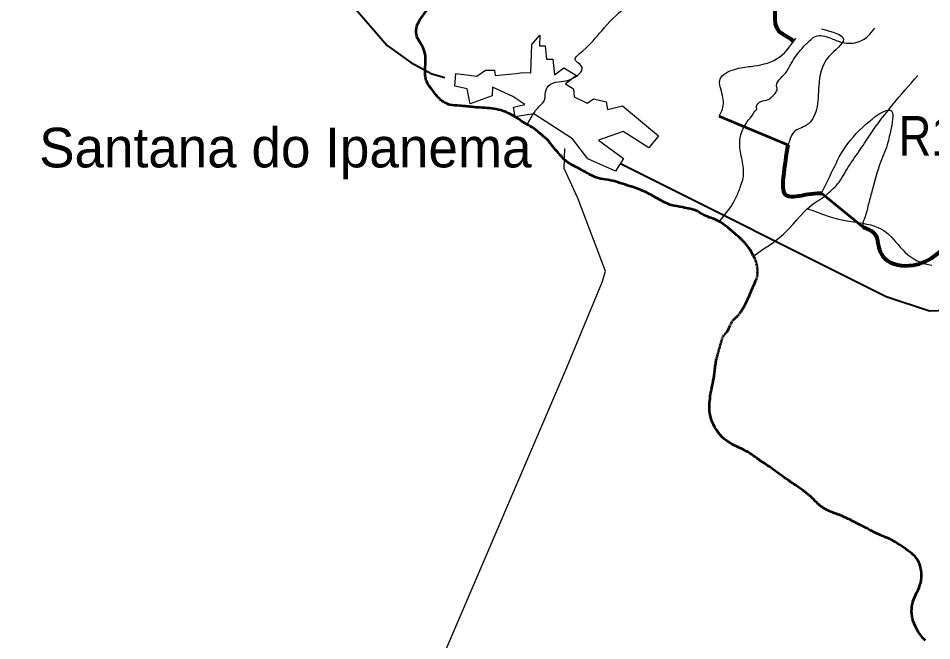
# Model space of a CAD drawing. Extents: x 553962 to 842807, y 8883888 to 9032388.
# Drawn here: x 685895 to 697411, y 8956803 to 8964653 of the extents above; entities that cross this region are included whole.
import ezdxf
from ezdxf.enums import TextEntityAlignment as Align

# ---------------------------------------------------------------- set-up
doc = ezdxf.new("R2010")
doc.units = 0
doc.header["$LTSCALE"] = 200
for name, color, linetype, lineweight in [('12', 7, 'Continuous', 25), ('21', 7, 'Continuous', 25), ('24', 7, 'Continuous', 25), ('50', 7, 'Continuous', 80), ('51', 7, 'Continuous', 25), ('9', 7, 'Continuous', 90)]:
    doc.layers.add(name, color=color, linetype=linetype, lineweight=lineweight)
doc.layers.add('41', color=7, linetype='Continuous')
doc.layers.add('53', color=7, linetype='Continuous')

msp = doc.modelspace()

# ---------------------------------------------------------------- linework, layer by layer
at = {"layer": '12', "lineweight": 40}
for points in [[(678613, 8973314.2), (678848.5, 8973159.5), (686496, 8968269.5), (688991.1, 8966516.2), (690142.8, 8964774.6), (690545.4, 8964311.7), (690844.1, 8964097.1), (691108, 8963953.4), (691274.5, 8963904.3)], [(693487.4, 8962819.8), (696836.9, 8961144.8), (697384.1, 8960961.8), (697603.7, 8960973.6), (697714.4, 8961082.3), (698321.2, 8961447.4), (698679, 8961567.8), (700187.3, 8961472.5), (701093.5, 8961547), (704410.2, 8961560.7)]]:
    msp.add_lwpolyline(points, dxfattribs=at)
at = {"layer": '12'}
msp.add_lwpolyline([(691240.8, 8956578.2), (692809.2, 8960246.9), (693257.6, 8961326.5), (693299.9, 8961463.3), (692951.1, 8962385.1), (692776, 8962756.9), (692786.9, 8963010.2)], dxfattribs=at)
at = {"layer": '21'}
msp.add_lwpolyline([(692254, 8963968.8), (692357.6, 8963964.3), (692367.8, 8964321.4), (692472.5, 8964438.4), (692467.8, 8964306.3), (692539.2, 8964305.6), (692555.6, 8964137.6), (692634.2, 8964137), (692654, 8963940.3), (692772.6, 8964028.6), (692932.6, 8963930.8), (692792.3, 8963824.8), (692895.4, 8963763.2), (692905.3, 8963663.2), (693068.9, 8963583.2), (693148, 8963636.1), (693304.9, 8963599), (693325.5, 8963502.4), (693511.7, 8963547.2), (693965.8, 8963171.8), (693843, 8963019.3), (693523.2, 8963225.7), (693211.4, 8963117.6), (693527.4, 8962882.7), (693426, 8962722.9), (693077.2, 8962879.5), (692882.8, 8963134.7), (692396, 8963446.1), (692159.9, 8963408.8), (692139.5, 8963534), (692282.7, 8963564.9), (692129.9, 8963666.3), (691873.7, 8963786.3), (691869.2, 8963675.7), (691593.2, 8963574.5), (691555.5, 8963764.1), (691398.6, 8963797.6), (691410.7, 8963954.6), (691678.4, 8963923.7), (691786.2, 8963997.8), (691900.5, 8963996.8), (691907.1, 8963932.5), (692171.7, 8963955.2)], close=True, dxfattribs=at)
at = {"layer": '24'}
for p, q in [((695185.1, 8961613.6), (695188.4, 8961605.4)), ((695191.4, 8961597.4), (695194.2, 8961589.4)), ((695196.8, 8961581.3), (695199.3, 8961572.8)), ((695201.7, 8961563.9), (695204, 8961554.7)), ((695206.1, 8961545.2), (695208.1, 8961535.5)), ((695210, 8961525.8), (695211.6, 8961516.2)), ((695213.1, 8961506.8), (695214.2, 8961497.7)), ((695208.8, 8961386.1), (695206.5, 8961378.2)), ((695212.3, 8961401), (695210.8, 8961393.7)), ((695214.3, 8961415.2), (695213.5, 8961408.2)), ((695215.5, 8961429.1), (695215, 8961422.2)), ((695215.1, 8961489), (695215.8, 8961480.6)), ((695216.2, 8961443), (695215.9, 8961436)), ((695216.2, 8961472.6), (695216.5, 8961464.9)), ((695216.5, 8961457.4), (695216.4, 8961450.1)), ((695203.7, 8961369.9), (695200.3, 8961361)), ((694988.2, 8960928.1), (694982.2, 8960920.1)), ((694881.6, 8960804.2), (694878.1, 8960796.7)), ((694888.3, 8960817.6), (694885, 8960811.2)), ((694895.4, 8960829.4), (694891.8, 8960823.7)), ((694903.2, 8960840.2), (694899.2, 8960834.8)), ((694912.2, 8960850.5), (694907.6, 8960845.4)), ((694922.1, 8960860.3), (694917.1, 8960855.5)), ((694932, 8960869.5), (694927, 8960865)), ((694941.4, 8960877.7), (694936.8, 8960873.7)), ((694950, 8960885.1), (694945.8, 8960881.5)), ((694958.2, 8960892.6), (694954.1, 8960888.7)), ((694966.8, 8960901.5), (694962.4, 8960896.8)), ((694976.7, 8960913), (694971.5, 8960906.9)), ((694825.8, 8960695.7), (694819.7, 8960688.5)), ((694874.5, 8960788.4), (694870.7, 8960779.5)), ((694761.3, 8960585.2), (694758.9, 8960576.3)), ((694767, 8960603.1), (694764, 8960594.1)), ((694773.6, 8960621), (694770.2, 8960612.1)), ((694781.6, 8960638.2), (694777.4, 8960629.7)), ((694790.9, 8960654), (694786, 8960646.3)), ((694801.8, 8960668.2), (694796.2, 8960661.2)), ((694813.6, 8960681.6), (694807.6, 8960674.9)), ((694728.6, 8960470), (694726.2, 8960462.1)), ((694733.8, 8960485.9), (694731.2, 8960478)), ((694738.8, 8960501.8), (694736.3, 8960493.8)), ((694743.7, 8960517.7), (694741.3, 8960509.7)), ((694748.1, 8960534), (694745.9, 8960525.8)), ((694752.2, 8960550.6), (694750.2, 8960542.3)), ((694756.5, 8960567.7), (694754.3, 8960559.1)), ((694699.2, 8960361.1), (694696.9, 8960351.9)), ((694703.5, 8960376.8), (694701.4, 8960369.2)), ((694707.7, 8960391.1), (694705.6, 8960383.9)), ((694711.6, 8960406), (694709.7, 8960398.4)), ((694715.5, 8960421.7), (694713.5, 8960413.8)), ((694719.5, 8960437.8), (694717.4, 8960429.8)), ((694723.8, 8960454.1), (694721.6, 8960446))]:
    msp.add_line(p, q, dxfattribs=at)
at = {"layer": '24', "lineweight": 53}
for p, q in [((695191.4, 8961597.4), (695188.4, 8961605.4)), ((695196.8, 8961581.3), (695194.2, 8961589.4)), ((695201.7, 8961563.9), (695199.3, 8961572.8)), ((695206.1, 8961545.2), (695204, 8961554.7)), ((695210, 8961525.8), (695208.1, 8961535.5)), ((695213.1, 8961506.8), (695211.6, 8961516.2)), ((695215.1, 8961489), (695214.2, 8961497.7)), ((695203.7, 8961369.9), (695206.5, 8961378.2)), ((695208.8, 8961386.1), (695210.8, 8961393.7)), ((695212.3, 8961401), (695213.5, 8961408.2)), ((695214.3, 8961415.2), (695215, 8961422.2)), ((695215.5, 8961429.1), (695215.9, 8961436)), ((695216.2, 8961472.6), (695215.8, 8961480.6)), ((695216.2, 8961443), (695216.4, 8961450.1)), ((695216.5, 8961457.4), (695216.5, 8961464.9)), ((694976.7, 8960913), (694982.2, 8960920.1)), ((694881.6, 8960804.2), (694885, 8960811.2)), ((694888.3, 8960817.6), (694891.8, 8960823.7)), ((694895.4, 8960829.4), (694899.2, 8960834.8)), ((694903.2, 8960840.2), (694907.6, 8960845.4)), ((694912.2, 8960850.5), (694917.1, 8960855.5)), ((694922.1, 8960860.3), (694927, 8960865)), ((694932, 8960869.5), (694936.8, 8960873.7)), ((694941.4, 8960877.7), (694945.8, 8960881.5)), ((694950, 8960885.1), (694954.1, 8960888.7)), ((694958.2, 8960892.6), (694962.4, 8960896.8)), ((694966.8, 8960901.5), (694971.5, 8960906.9)), ((694813.6, 8960681.6), (694819.7, 8960688.5)), ((694874.5, 8960788.4), (694878.1, 8960796.7)), ((694756.5, 8960567.7), (694758.9, 8960576.3)), ((694761.3, 8960585.2), (694764, 8960594.1)), ((694767, 8960603.1), (694770.2, 8960612.1)), ((694773.6, 8960621), (694777.4, 8960629.7)), ((694781.6, 8960638.2), (694786, 8960646.3)), ((694790.9, 8960654), (694796.2, 8960661.2)), ((694801.8, 8960668.2), (694807.6, 8960674.9)), ((694723.8, 8960454.1), (694726.2, 8960462.1)), ((694728.6, 8960470), (694731.2, 8960478)), ((694733.8, 8960485.9), (694736.3, 8960493.8)), ((694738.8, 8960501.8), (694741.3, 8960509.7)), ((694743.7, 8960517.7), (694745.9, 8960525.8)), ((694748.1, 8960534), (694750.2, 8960542.3)), ((694752.2, 8960550.6), (694754.3, 8960559.1)), ((694699.2, 8960361.1), (694701.4, 8960369.2)), ((694703.5, 8960376.8), (694705.6, 8960383.9)), ((694707.7, 8960391.1), (694709.7, 8960398.4)), ((694711.6, 8960406), (694713.5, 8960413.8)), ((694715.5, 8960421.7), (694717.4, 8960429.8)), ((694719.5, 8960437.8), (694721.6, 8960446))]:
    msp.add_line(p, q, dxfattribs=at)
at = {"layer": '24'}
for points in [[(695169, 8961656.4), (695276, 8961734.9), (695379, 8961800.8), (695467.1, 8961866.7), (695542.4, 8961931.7), (695606.8, 8961994.7), (695662.7, 8962054.9), (695711.8, 8962111.2), (695756.5, 8962162.8), (695798.7, 8962208.5), (695840.2, 8962247.9), (695844.8, 8962251.7), (695925.7, 8962224.4), (696035.2, 8962181.1), (696132.7, 8962148.6), (696219.6, 8962124.8), (696297.2, 8962107.9), (696367.1, 8962095.8), (696430.6, 8962086.5), (696489, 8962078.1), (696543.7, 8962068.8), (696595, 8962058.2), (696643, 8962046), (696688, 8962031.9), (696729.9, 8962015.6), (696769, 8961997.1), (696805.5, 8961975.9), (696839.5, 8961951.8), (696871.2, 8961924.8), (696901.1, 8961895.4), (696929.9, 8961864), (696958.1, 8961831.5), (696986.4, 8961798.2), (697015.3, 8961765), (697045.4, 8961732.3), (697077.4, 8961700.9), (697111.7, 8961671.2), (697148.3, 8961643.6), (697187.3, 8961618.4), (697228.5, 8961595.8)], [(695116.9, 8961748), (695124.2, 8961736.8), (695131.2, 8961725.1), (695138.1, 8961712.9), (695144.8, 8961700.5), (695151.1, 8961688), (695157.2, 8961675.6), (695162.9, 8961663.6), (695168.2, 8961652.1)], [(697228.5, 8961595.8), (697272, 8961576.2), (697317.5, 8961559.7), (697365.1, 8961546.7), (697414.7, 8961537.5)]]:
    msp.add_lwpolyline(points, dxfattribs=at)
at = {"layer": '24', "lineweight": 53}
for points in [[(695185.1, 8961613.6), (695181.5, 8961622.3), (695177.5, 8961631.4), (695173.1, 8961641.4), (695168.2, 8961652.1)], [(694988.2, 8960928.1), (694994.5, 8960936.7), (695001, 8960945.8), (695007.6, 8960955.3), (695014.2, 8960965), (695020.7, 8960974.9), (695027, 8960984.7), (695033.1, 8960994.3), (695039.1, 8961004.1), (695045.1, 8961014.5), (695051.4, 8961025.8), (695057.9, 8961038.3), (695065, 8961052.5), (695072.8, 8961068.8), (695081.4, 8961087.4), (695091, 8961108.7), (695101.2, 8961132), (695112, 8961156.7), (695123, 8961182.2), (695134, 8961207.7), (695144.6, 8961232.5), (695154.7, 8961256.1), (695164, 8961277.6), (695172.3, 8961296.5), (695179.6, 8961313), (695186, 8961327.5), (695191.5, 8961340.1), (695196.2, 8961351.1), (695200.3, 8961361)], [(694825.8, 8960695.7), (694831.7, 8960703.3), (694837.5, 8960711.5), (694843, 8960720.4), (694848.2, 8960730), (694853.2, 8960739.8), (694858, 8960749.9), (694862.5, 8960760), (694866.7, 8960769.9), (694870.7, 8960779.5)], [(694610.5, 8959801.8), (694612.9, 8959833), (694616.2, 8959863.1), (694620.1, 8959891.9), (694624.3, 8959919.5), (694628.9, 8959945.6), (694633.6, 8959970.2), (694638.3, 8959993.2), (694642.9, 8960014.6), (694647.3, 8960034.3), (694651.3, 8960052.2), (694654.8, 8960068.3), (694657.9, 8960082.9), (694660.6, 8960096.7), (694663.1, 8960109.9), (694665.3, 8960123.1), (694667.5, 8960136.7), (694669.5, 8960151.2), (694671.6, 8960167.1), (694673.7, 8960184.6), (694675.9, 8960203.4), (694678.2, 8960223), (694680.5, 8960243), (694682.8, 8960262.7), (694685.2, 8960281.7), (694687.6, 8960299.4), (694689.9, 8960315.5), (694692.3, 8960329.4), (694694.6, 8960341.5), (694696.9, 8960351.9)], [(695412.6, 8958963.5), (695390.1, 8958979.4), (695368.3, 8958994.5), (695347.1, 8959009), (695326.3, 8959023.1), (695305.9, 8959036.8), (695285.8, 8959050.4), (695265.9, 8959063.9), (695246.1, 8959077.5), (695226.2, 8959091.4), (695206.1, 8959105.7), (695185.8, 8959120.3), (695164.8, 8959135.2), (695143.1, 8959150.1), (695120.4, 8959165), (695096.6, 8959179.9), (695071.3, 8959194.5), (695044.4, 8959208.8), (695015.8, 8959222.9), (694985.9, 8959236.9), (694954.9, 8959251.4), (694923.4, 8959266.7), (694891.7, 8959283.3), (694860.2, 8959301.5), (694829.4, 8959321.8), (694799.7, 8959344.6), (694771.4, 8959370.2), (694744.8, 8959398.3), (694720.1, 8959428.6), (694697.5, 8959460.6), (694677.2, 8959494), (694659.3, 8959528.4), (694644.1, 8959563.4), (694631.8, 8959598.6), (694622.4, 8959633.7), (694615.8, 8959668.4), (694611.6, 8959702.8), (694609.5, 8959736.5), (694609.3, 8959769.6), (694610.5, 8959801.8)], [(695976.9, 8958531), (695967.2, 8958540.1), (695957.7, 8958549.4), (695948.1, 8958558.9), (695938.5, 8958568.5), (695928.9, 8958578.1), (695919.2, 8958587.8), (695909.4, 8958597.3), (695899.5, 8958606.6), (695889.5, 8958615.8), (695879.4, 8958624.8), (695869.1, 8958633.6), (695858.8, 8958642.3), (695848.4, 8958650.8), (695837.9, 8958659.2), (695827.4, 8958667.5), (695816.9, 8958675.7), (695806.4, 8958683.8), (695795.7, 8958692), (695784.8, 8958700.2), (695773.5, 8958708.6), (695761.6, 8958717.3), (695749.1, 8958726.3), (695735.9, 8958735.7), (695721.7, 8958745.6), (695706.5, 8958756), (695690.3, 8958767), (695673.1, 8958778.7), (695655, 8958791), (695636, 8958803.9), (695616.2, 8958817.6), (695595.5, 8958832), (695574, 8958847.1), (695551.8, 8958862.9), (695529, 8958879.4), (695505.8, 8958896.2), (695482.3, 8958913.2), (695458.9, 8958930.2), (695435.6, 8958947.1), (695412.6, 8958963.5)], [(696565.6, 8958234), (696553, 8958240.7), (696540.1, 8958247.5), (696526.7, 8958254.6), (696512.5, 8958262), (696497.3, 8958269.9), (696480.9, 8958278.4), (696462.9, 8958287.6), (696443.2, 8958297.7), (696422.1, 8958308.3), (696399.9, 8958319.3), (696377.1, 8958330.5), (696354, 8958341.7), (696331, 8958352.5), (696308.5, 8958362.8), (696286.8, 8958372.3), (696266.3, 8958381), (696247, 8958388.7), (696228.8, 8958395.7), (696211.6, 8958402.1), (696195.3, 8958408), (696179.9, 8958413.6), (696165.2, 8958418.8), (696151.3, 8958424), (696138, 8958429.1), (696125.3, 8958434.3), (696113, 8958439.6), (696101.2, 8958445), (696089.8, 8958450.5), (696078.8, 8958456.3), (696067.9, 8958462.3), (696057.3, 8958468.6), (696046.9, 8958475.3), (696036.5, 8958482.3), (696026.3, 8958489.6), (696016.2, 8958497.3), (696006.3, 8958505.3), (695996.4, 8958513.5), (695986.6, 8958522.1), (695976.9, 8958531)], [(697236.7, 8957815.1), (697224.9, 8957833.8), (697211.5, 8957851.4), (697196.4, 8957868.2), (697179.4, 8957884.7), (697160.2, 8957901.4), (697138.7, 8957918.7), (697114.9, 8957936.9), (697089.2, 8957955.7), (697062.3, 8957974.8), (697034.9, 8957993.6), (697007.6, 8958011.9), (696981, 8958029.1), (696955.8, 8958044.8), (696932.7, 8958058.6), (696912.1, 8958070.2), (696893.7, 8958079.8), (696877.2, 8958087.9), (696862.2, 8958094.6), (696848.2, 8958100.5), (696834.9, 8958105.8), (696821.7, 8958110.9), (696808.4, 8958116.1), (696794.5, 8958121.7), (696780.1, 8958127.8), (696765.2, 8958134.2), (696750.2, 8958141), (696734.9, 8958148), (696719.6, 8958155.2), (696704.3, 8958162.5), (696689.2, 8958169.8), (696674.4, 8958177.2), (696659.8, 8958184.6), (696645.5, 8958191.9), (696631.5, 8958199.1), (696617.8, 8958206.3), (696604.3, 8958213.4), (696591.2, 8958220.4), (696578.3, 8958227.2), (696565.6, 8958234)], [(697331.3, 8956805.9), (697323.2, 8956813.3), (697314.3, 8956822.1), (697304.5, 8956832.4), (697293.7, 8956844.7), (697281.9, 8956859.2), (697269, 8956876.1), (697255.3, 8956895.4), (697241.2, 8956916.7), (697227.2, 8956940), (697213.5, 8956965.1), (697200.6, 8956991.7), (697188.9, 8957019.6), (697178.8, 8957048.7), (697170.6, 8957078.7), (697164.4, 8957109.5), (697160.3, 8957140.9), (697158.5, 8957172.5), (697159, 8957204.3), (697161.8, 8957236), (697167.1, 8957267.4), (697175, 8957298.3), (697185.4, 8957328.5), (697197.7, 8957358.2), (697211.2, 8957387.5), (697225.2, 8957416.7), (697239.1, 8957446), (697252, 8957475.4), (697263.2, 8957505.3), (697272.1, 8957535.8), (697278.2, 8957567), (697281.4, 8957598.5), (697282.1, 8957630), (697280.5, 8957661.1), (697276.8, 8957691.2), (697271.4, 8957720), (697264.5, 8957747.1), (697256.3, 8957772.1), (697247.1, 8957794.6), (697236.7, 8957815.1)]]:
    msp.add_lwpolyline(points, dxfattribs=at)
msp.add_spline([(695170.7, 8961646.8), (695094.7, 8961773.3), (694929.1, 8961938.8), (694680.8, 8962114.8), (694540.3, 8962171.7), (694427.3, 8962232.6), (694366.5, 8962247.8), (694270.9, 8962269.5), (694127.6, 8962297.8), (693938.6, 8962389.1), (693764.8, 8962478.2), (693575.8, 8962545.5), (693330.4, 8962615.1), (693210.9, 8962636.8), (692989.3, 8962745.5), (692906.8, 8962786.8), (692817.7, 8962838.9), (692765.6, 8962886.7), (692691.7, 8962969.3), (692639.6, 8963030.2), (692544, 8963141), (692498.4, 8963178), (692402.8, 8963258.4), (692300.7, 8963319.2), (692140, 8963421.4), (691977.1, 8963493.1), (691866.3, 8963514.8), (691638.2, 8963532.2), (691462.3, 8963549.6), (691336.3, 8963562.6), (691273.3, 8963588.7), (691203.8, 8963640.9), (691103.8, 8963762.6), (691048.1, 8963842.5), (691024.9, 8963935.4), (691027.8, 8964068.8), (691022, 8964216.8), (690966.8, 8964338.7), (690920.4, 8964422.8), (690914.6, 8964530.2), (690952.3, 8964623), (691022, 8964721.7), (691088.7, 8964808.7), (691297.6, 8965101.8), (691483.3, 8965383.2), (691582, 8965539.9), (691761.8, 8965929.2), (692017.2, 8966518.5), (692139.1, 8966942.3), (692231.9, 8967543.3), (692246.4, 8967740.7), (692124.5, 8967943.9), (691973.7, 8968039.7), (691700.9, 8968077.4), (691448.5, 8968103.5)], degree=3, dxfattribs=at)
at = {"layer": '24'}
for points in [[(692309.3, 8963314.4), (692463.9, 8963541.7), (692531, 8963625.6), (692542.2, 8963720.6), (692603.7, 8963821.3), (692743.5, 8963854.8), (692844.1, 8963877.2), (692944.8, 8963933.1), (693006.3, 8964017), (692961.6, 8964084.1), (692916.8, 8964134.4), (692972.7, 8964207.1), (693224.3, 8964464.2), (693509.5, 8964755), (693727.5, 8964973.1), (693738.7, 8965112.8), (693822.6, 8965342.1), (694079.8, 8965632.8), (694225.2, 8965783.8), (694415.2, 8966001.8), (694560.6, 8966180.7), (694706, 8966376.4), (694935.2, 8966560.9), (695192.4, 8966717.5), (695455.2, 8966997.1), (695650.9, 8967226.3), (695768.8, 8967390)], [(694734.6, 8962088.7), (694951.1, 8962403.9), (695005.7, 8962547), (695033.3, 8962637), (695026.4, 8962837.6), (694991.8, 8963045.2), (695005.7, 8963183.6), (695102.5, 8963370.4), (695172.1, 8963468), (695188.8, 8963491.9), (695200.7, 8963496.7), (695203.1, 8963542.1), (695224.6, 8963580.3), (695258, 8963604.2), (695348.8, 8963628.2), (695391.8, 8963659.2), (695449.1, 8963723.8), (695463.5, 8963766.8), (695458.7, 8963781.1), (695566.2, 8963960.4), (695640.2, 8964082.3), (695776.4, 8964273.5), (695876.7, 8964373.9), (695934.1, 8964419.3), (696015.3, 8964436.1), (696113.2, 8964412.2), (696251.8, 8964357.2), (696364, 8964338.1), (696469.1, 8964350), (696543.2, 8964381.1), (696607.7, 8964428.9), (696693.7, 8964529.3)], [(695842.1, 8962251.3), (695941.2, 8962329.7), (696048.4, 8962395.7), (696135, 8962474.1), (696205.1, 8962540.1), (696341.1, 8962746.4), (696493.7, 8962973.3), (696629.8, 8963179.6), (697235.9, 8963930.5)]]:
    msp.add_spline(points, degree=3, dxfattribs=at)
at = {"layer": '50'}
for points in [[(695074.8, 8965348.6), (695081, 8965093.8), (695256.6, 8965033), (695407.2, 8964921.4), (695478.6, 8964495.4), (695634.2, 8964393.9), (695663.2, 8964365.8)], [(696547.7, 8962020.4), (696708.3, 8961913.9), (696738.8, 8961782.1), (696819.4, 8961624.8), (697175.4, 8961538.6), (697715.6, 8961919), (698200.2, 8962441.3), (698505.4, 8962613.7), (699061, 8962852.1), (699386.2, 8963024.5), (699670.8, 8963399.8), (699765.8, 8963465.7)], [(695597.8, 8963055.1), (695538.8, 8962639.2), (695564.4, 8962431.3), (695804.9, 8962426.2), (695970.2, 8962446.5), (696025.4, 8962446.5)]]:
    msp.add_spline(points, degree=3, dxfattribs=at)
at = {"layer": '51'}
for p, q in [((695597.8, 8963055.1), (694729.8, 8963420.2)), ((696547.7, 8962020.4), (696020.4, 8962446.5))]:
    msp.add_line(p, q, dxfattribs=at)
at = {"layer": '51', "lineweight": 53}
for p, q in [((694729.8, 8963420.2), (695597.8, 8963055.1)), ((696020.4, 8962446.5), (696547.7, 8962020.4))]:
    msp.add_line(p, q, dxfattribs=at)
at = {"layer": '51'}
for points in [[(696023, 8964519.8), (696298.2, 8964387.7), (696115.8, 8964170.8), (695986.6, 8963800.6), (695957.3, 8963501.3), (695832.6, 8963303.6), (695672.5, 8963217.3), (695622.6, 8963121), (695597.8, 8963055.1)], [(694729.8, 8963420.2), (694764.7, 8963486.2), (694774.2, 8963678.9), (694743.6, 8963886.8), (694923.7, 8964008.5), (695131.5, 8964046.2), (695456.2, 8964139.8), (695698.3, 8964404.2)], [(696020.4, 8962446.5), (696184.8, 8962781.2), (696391.8, 8963121), (696914.6, 8963468), (696881.6, 8963187.1), (696859.6, 8963088), (696765.9, 8962836.9), (696656.7, 8962466.7), (696612.1, 8962299.4), (696562.4, 8962126.9), (696542.6, 8962050.8), (696547.7, 8962020.4)]]:
    msp.add_spline(points, degree=3, dxfattribs=at)
at = {"layer": '9'}
for points in [[(637260.6, 8972975.8), (641524.5, 8971056.2), (652526.1, 8965412.7), (653164.3, 8965062.8), (670790.5, 8953770.1), (686194, 8943929.9), (696283.3, 8937647.1)], [(694874, 8947402.7), (694491.4, 8947729), (693981.6, 8948105.1), (692654.2, 8949437.3), (691811.8, 8950292), (691552.9, 8951277.6), (691093.4, 8951755.3), (689976, 8951721.8), (689441.2, 8951996.3), (689158.9, 8952576.6), (688699.5, 8953029), (687605.5, 8953400.8), (685873.4, 8954400.8), (684752.3, 8955101.5), (681638, 8958243.7), (680641.1, 8959527.7), (679425.4, 8960995.9)]]:
    msp.add_spline(points, degree=3, dxfattribs=at)

# ---------------------------------------------------------------- texts
at = {"layer": '41'}
msp.add_text('Santana do Ipanema', height=500, dxfattribs=at).set_placement((686158.2, 8962772.4))
at = {"layer": '53', "width": 0.85}
msp.add_text('R15b', height=500, dxfattribs=at).set_placement((697675.3, 8962920.1), align=Align.CENTER)

doc.saveas('drawing.dxf')
